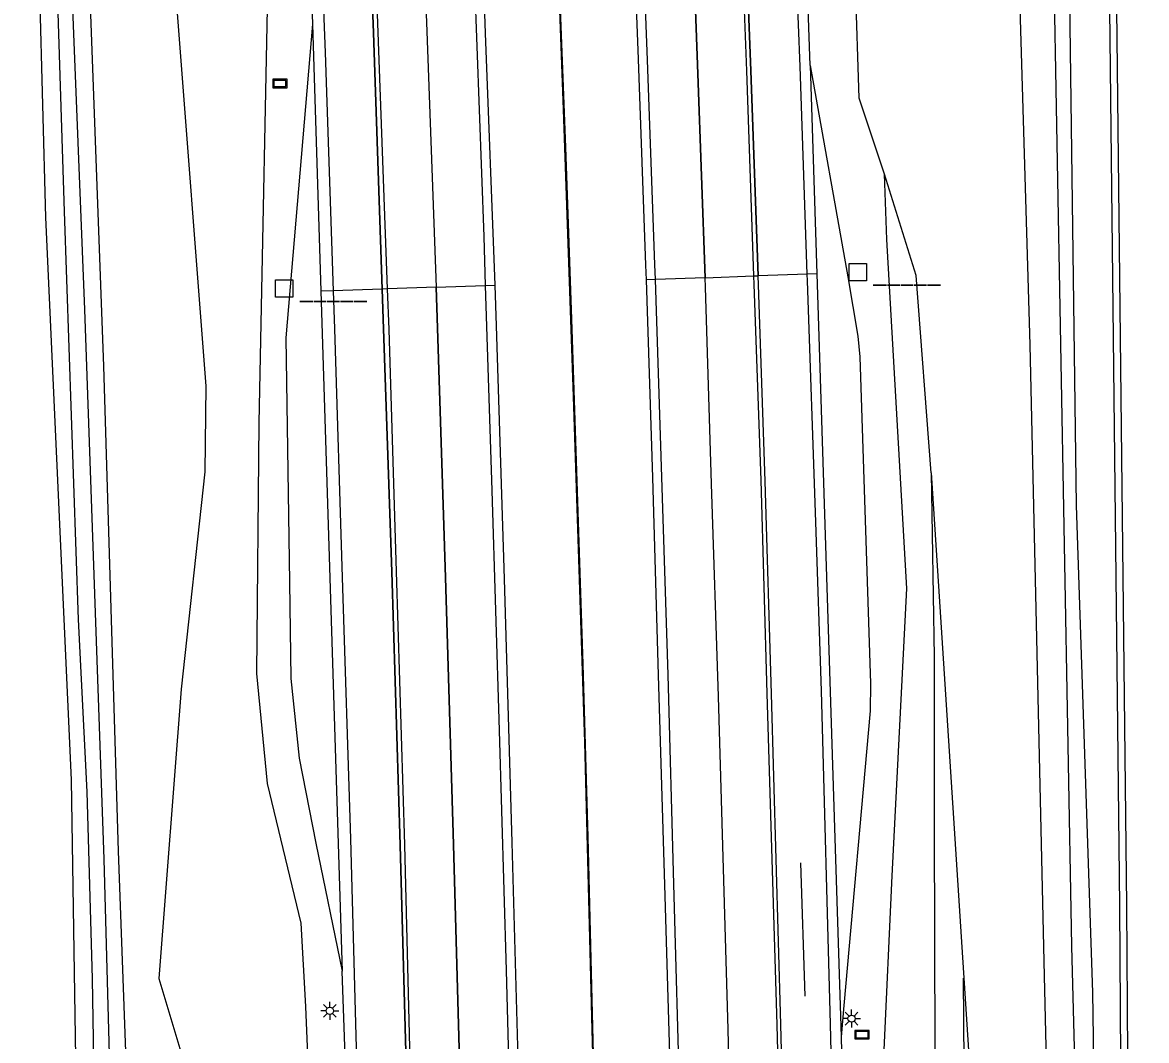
# Model space of a CAD drawing. Extents: x 133000 to 136000, y 400500 to 403500.
# Drawn here: x 133107.2 to 133185.2, y 401903.1 to 401973.7 of the extents above; entities that cross this region are included whole.
import ezdxf

# ---------------------------------------------------------------- set-up
doc = ezdxf.new("R2010")
doc.units = 0
for name, color, linetype in [('gg-afsc-lijn draadraster', 7, 'Continuous'), ('gt-knt-geleideconstructie', 7, 'Continuous'), ('gt-symb-bord', 7, 'Continuous'), ('gt-symb-hm paal', 7, 'Continuous'), ('gt-symb-lichtmast', 7, 'Continuous'), ('gx-grn-maaiveld', 7, 'Continuous'), ('gx-knt-lijn weginrichtingselement', 7, 'Continuous')]:
    doc.layers.add(name, color=color, linetype=linetype)

# ---------------------------------------------------------------- blocks, each defined once
blk = doc.blocks.new('gt0-HMpaal')
at = {"layer": 'gt-symb-hm paal'}
blk.add_lwpolyline([(-0.6, 0.6), (0.6, 0.6), (0.6, -0.6), (-0.6, -0.6)], close=True, dxfattribs=at)
blk = doc.blocks.new('gt0-BORD')
at = {"layer": 'gt-symb-bord'}
blk.add_lwpolyline([(-0.5, 0.295), (-0.5, -0.295), (0.5, -0.295), (0.5, 0.295), (-0.5, 0.295)], dxfattribs=at)
blk.add_lwpolyline([(-0.417, -0.212), (0.417, -0.212), (0.417, 0.212), (-0.417, 0.212)], close=True, dxfattribs=at)
blk = doc.blocks.new('gt0-LMAST')
at = {"layer": 'gt-symb-lichtmast'}
for p, q in [((-0.182, 0.173), (-0.447, 0.438)), ((-0.005, 0.246), (-0.005, 0.621)), ((0.172, 0.173), (0.437, 0.438)), ((-0.255, -0.004), (-0.63, -0.004)), ((-0.182, -0.181), (-0.447, -0.446)), ((-0.005, -0.254), (-0.005, -0.629)), ((0.437, -0.446), (0.172, -0.181)), ((0.245, -0.004), (0.62, -0.004))]:
    blk.add_line(p, q, dxfattribs=at)
blk.add_circle((-0.005, -0.004), 0.25, dxfattribs=at)

msp = doc.modelspace()

# ---------------------------------------------------------------- linework, layer by layer
at = {"layer": 'gg-afsc-lijn draadraster'}
msp.add_lwpolyline([(133174.016, 401805.443), (133174.136, 401808.549), (133174.159, 401809.14), (133174.172, 401813.522), (133174.109, 401818.318), (133173.692, 401850.139), (133172.627, 401894.902), (133172.575, 401901.522), (133172.528, 401907.403)], dxfattribs=at)
at = {"layer": 'gt-knt-geleideconstructie'}
msp.add_lwpolyline([(133149.363, 401793.243), (133149.083, 401805.224), (133148.887, 401817.242), (133148.636, 401829.227), (133148.416, 401841.232), (133148.091, 401853.218), (133147.822, 401865.204), (133147.496, 401877.215), (133147.225, 401889.21), (133146.87, 401901.198), (133146.493, 401917.197), (133146.145, 401929.19), (133145.738, 401941.185), (133145.363, 401953.153), (133144.94, 401965.088), (133144.484, 401977.083)], dxfattribs=at)
at = {"layer": 'gx-grn-maaiveld'}
for p, q in [((133127.358, 401973.624), (133127.939, 401955.086)), ((133161.889, 401970.754), (133162.35, 401956.298)), ((133162.35, 401956.298), (133164.04, 401903.323)), ((133127.939, 401955.086), (133129.417, 401907.897))]:
    msp.add_line(p, q, dxfattribs=at)
for points in [[(133176.05, 402057.04), (133177.396, 402032.031), (133178.512, 402008.898), (133179.703, 401989.356), (133180.341, 401940.214), (133181.464, 401906.415), (133181.539, 401901.715), (133182.254, 401857.402), (133183.35, 401809.953), (133183.229, 401809.552), (133183.03, 401809.332), (133182.798, 401809.261), (133182.54, 401809.296), (133182.302, 401809.634), (133181.77, 401846.486), (133180.249, 401901.687), (133180.03, 401909.629), (133178.78, 401979.281), (133178.419, 401989.728), (133177.792, 402004.82), (133177.249, 402019.981), (133176.408, 402036.174), (133175.693, 402050.241), (133175.359, 402057.017)], [(133146.351, 402055.862), (133146.989, 402042.445), (133147.593, 402028.479), (133148.206, 402014.746), (133148.796, 402000.86), (133149.367, 401986.341), (133149.963, 401971.194), (133150.47, 401956.9), (133150.504, 401955.876)], [(133150.439, 402056.066), (133150.913, 402045.905), (133151.57, 402031.837), (133152.248, 402016.696), (133152.92, 402000.007), (133153.564, 401984.746), (133154.094, 401970.177), (133154.598, 401956.022)], [(133154.139, 402056.25), (133154.603, 402046.055), (133155.303, 402031.823), (133155.951, 402016.736), (133156.613, 402000.091), (133157.227, 401984.859), (133157.781, 401970.375), (133158.29, 401956.154)], [(133161.889, 401970.754), (133161.382, 401985.289), (133160.739, 402000.389), (133160.074, 402016.844), (133159.413, 402032.013), (133158.774, 402046.182), (133158.241, 402056.455)], [(133128.099, 402054.964), (133128.101, 402054.915), (133128.74, 402041.054), (133129.565, 402023.279), (133130.265, 402006.486), (133130.993, 401988.979), (133131.596, 401973.015), (133132.203, 401955.236)], [(133131.81, 402055.151), (133131.816, 402055.024), (133132.441, 402041.171), (133133.263, 402023.294), (133133.974, 402006.566), (133134.689, 401989.085), (133135.302, 401973.111), (133135.93, 401955.367)], [(133135.897, 402055.357), (133135.922, 402054.854), (133136.531, 402041.262), (133137.36, 402023.486), (133138.085, 402006.765), (133138.777, 401989.132), (133139.348, 401972.996), (133140.006, 401955.51)], [(133108.363, 402054.325), (133108.468, 402052.323), (133110.209, 402015.35), (133111.655, 401982.461), (133112.857, 401949.877), (133113.884, 401916.225), (133114.467, 401900.414), (133115.394, 401875.299), (133116.395, 401826.398), (133115.699, 401816.238), (133115.91, 401815.754), (133116.719, 401815.324), (133124.581, 401816.316), (133125.023, 401816.019), (133125.204, 401815.496), (133125.11, 401810.457), (133124.98, 401810.092), (133124.48, 401809.894), (133118.918, 401810.424), (133114.126, 401811.625), (133112.802, 401812.751)], [(133112.963, 402054.452), (133114.085, 402025.85), (133117.578, 401989.274), (133117.943, 401974.682), (133119.969, 401948.497), (133119.889, 401942.54), (133118.252, 401927.473), (133116.694, 401907.374), (133118.792, 401900.446), (133119.487, 401898.152), (133122.312, 401893.701), (133123.783, 401889.955), (133123.969, 401883.825), (133125.155, 401850.739), (133126.285, 401824.409), (133126.07, 401808.221), (133125.464, 401807.237)], [(133121.296, 402054.731), (133122.517, 402034.095), (133123.546, 402004.084), (133124.348, 401981.599), (133123.643, 401945.952), (133123.481, 401928.541), (133124.211, 401920.925), (133126.555, 401911.214), (133126.865, 401905.448), (133127.29, 401895.389), (133128.724, 401847.354), (133129.414, 401810.458), (133129.765, 401808.488), (133129.93, 401807.918), (133129.99, 401802.659), (133129.505, 401793.52), (133129.915, 401767.084), (133130.438, 401731.107), (133130.443, 401730.556)], [(133123.981, 402054.757), (133124.618, 402040.726), (133125.415, 402023.421), (133126.167, 402006.041), (133126.853, 401988.792), (133127.358, 401973.624)], [(133167.047, 401963.208), (133165.283, 401968.487), (133165.029, 401976.411), (133164.634, 401985.999), (133163.742, 402003.579), (133163.113, 402018.097), (133162.041, 402032.047), (133162.118, 402036.867), (133163.133, 402041.701), (133165.122, 402042.809), (133166.748, 402041.307), (133168.46, 402036.479), (133170.348, 402028.458), (133170.988, 402020.917), (133172.554, 402019.904), (133174.556, 402019.191)], [(133179.637, 402012.29), (133179.74, 402010.493), (133182.516, 401987.151), (133183.359, 401912.431), (133183.425, 401901.755), (133183.636, 401867.984), (133185.223, 401812.521), (133184.372, 401808.818), (133182.828, 401807.782), (133181.607, 401807.848), (133180.898, 401808.562)], [(133183.938, 401902.016), (133183.859, 401912.435), (133183.016, 401987.184), (133182.183, 401997.995)], [(133110.957, 401900.388), (133110.651, 401921.172), (133108.856, 401960.206), (133108.226, 401983.696), (133107.241, 401997.394)], [(133112.209, 401900.397), (133112.096, 401907.347), (133111.728, 401920.347), (133111.132, 401932.305), (133110.159, 401960.622), (133109.124, 401993.28)], [(133110.29, 401985.155), (133111.535, 401953.808), (133112.874, 401915.654), (133113.31, 401900.406)], [(133176.44, 401974.763), (133177.12, 401951.36), (133178.099, 401908.566), (133178.26, 401901.644), (133179.216, 401860.691), (133180.337, 401813.008), (133180.436, 401810.51), (133180.898, 401808.562)], [(133127.358, 401973.624), (133127.266, 401972.538), (133125.505, 401951.847), (133125.761, 401934.892), (133125.858, 401928.206), (133126.437, 401922.678), (133127.587, 401916.769), (133129.417, 401907.897)], [(133161.889, 401970.754), (133164.498, 401956.075), (133165.189, 401951.973), (133165.345, 401950.528), (133166.068, 401927.867), (133166.043, 401925.963), (133164.214, 401905.518), (133164.04, 401903.323)], [(133169.976, 401732.377), (133169.109, 401765.25), (133168.734, 401799.659), (133169.145, 401809.488), (133168.849, 401814.908), (133168.404, 401825.818), (133167.837, 401856.684), (133166.993, 401901.918), (133167.581, 401914.498), (133168.597, 401934.441), (133167.211, 401958.665), (133167.047, 401963.208)], [(133170.288, 401942.471), (133169.239, 401956.169), (133167.047, 401963.208)], [(133154.598, 401956.022), (133151.154, 401955.899), (133150.504, 401955.876)], [(133154.598, 401956.022), (133157.959, 401956.142), (133158.29, 401956.154)], [(133157.394, 401855.941), (133157.328, 401859.155), (133156.961, 401873.55), (133156.568, 401888.599), (133156.19, 401903.839), (133155.529, 401926.953), (133155.051, 401941.724), (133154.621, 401955.376), (133154.598, 401956.022)], [(133162.35, 401956.298), (133161.677, 401956.274), (133158.29, 401956.154)], [(133161.094, 401856.022), (133161.034, 401858.812), (133160.674, 401873.791), (133160.255, 401888.751), (133159.854, 401904.18), (133159.203, 401927.149), (133158.768, 401941.899), (133158.312, 401955.528), (133158.29, 401956.154)], [(133132.203, 401955.236), (133128.805, 401955.116), (133127.939, 401955.086)], [(133135.93, 401955.367), (133132.567, 401955.248), (133132.203, 401955.236)], [(133132.203, 401955.236), (133132.297, 401952.47), (133132.868, 401935.611), (133133.451, 401916.626), (133133.918, 401898.907), (133134.496, 401876.52), (133134.825, 401863.048), (133134.972, 401856.385), (133134.993, 401855.448)], [(133135.93, 401955.367), (133139.349, 401955.487), (133140.006, 401955.51)], [(133138.725, 401855.526), (133138.706, 401856.502), (133138.52, 401863.073), (133138.223, 401876.539), (133137.628, 401899.161), (133137.149, 401916.691), (133136.579, 401935.22), (133136.03, 401952.529), (133135.93, 401955.367)], [(133140.006, 401955.51), (133140.113, 401952.671), (133140.649, 401935.129), (133141.189, 401916.824), (133141.687, 401899.334), (133142.302, 401876.699), (133142.603, 401863.517), (133142.717, 401856.878), (133142.747, 401855.61)], [(133150.504, 401955.876), (133150.955, 401942.153), (133151.353, 401928.431), (133151.789, 401913.876), (133152.253, 401898.191), (133152.613, 401883.94), (133152.952, 401869.743), (133153.291, 401855.852)], [(133170.288, 401942.471), (133172.964, 401900.965), (133173.886, 401854.111), (133174.834, 401817.956), (133176.134, 401815.052), (133177.888, 401812.555)], [(133170.288, 401942.471), (133170.487, 401929.702), (133170.48, 401917.896), (133170.539, 401902.464), (133171.233, 401863.66), (133171.471, 401829.718), (133171.878, 401823.078), (133172.733, 401818.118), (133173.1, 401812.674), (133173.124, 401809.183), (133173.169, 401807.366), (133173.729, 401805.633)], [(133130.857, 401855.362), (133130.826, 401856.732), (133130.675, 401862.836), (133130.362, 401876.635), (133129.752, 401898.785), (133129.417, 401907.897)], [(133164.04, 401903.323), (133164.366, 401888.863), (133164.766, 401873.871), (133165.114, 401859.052), (133165.186, 401856.11)]]:
    msp.add_lwpolyline(points, dxfattribs=at)
at = {"layer": 'gx-knt-lijn weginrichtingselement'}
msp.add_line((133161.548, 401906.153), (133161.232, 401915.406), dxfattribs=at)
for points in [[(133127.567, 401988.844), (133128.238, 401971.659), (133128.805, 401955.116), (133128.896, 401952.472), (133129.409, 401935.22), (133129.997, 401917.076), (133130.494, 401899.137), (133131.094, 401876.752), (133131.421, 401862.892), (133131.576, 401856.676), (133131.604, 401855.378), (133131.963, 401838.577), (133132.335, 401822.287), (133132.634, 401804.83), (133133.616, 401788.133), (133134.435, 401772.977), (133135.396, 401755.749), (133135.419, 401755.363), (133136.381, 401739.008), (133136.862, 401730.852)], [(133137.066, 401731.048), (133136.977, 401739.077), (133136.79, 401755.4), (133136.787, 401755.654), (133136.567, 401772.95), (133136.36, 401787.918), (133136.044, 401804.647), (133135.711, 401822.363), (133135.378, 401838.312), (133134.993, 401855.448), (133134.972, 401856.385), (133134.825, 401863.048), (133134.496, 401876.52), (133133.918, 401898.907), (133133.451, 401916.626), (133132.868, 401935.611), (133132.297, 401952.47), (133132.203, 401955.236), (133131.596, 401973.015), (133130.993, 401988.979)], [(133137.358, 401730.875), (133137.28, 401739.006), (133137.104, 401755.408), (133137.101, 401755.703), (133136.859, 401772.888), (133136.659, 401787.704), (133136.341, 401804.597), (133136.04, 401822.554), (133135.676, 401838.435), (133135.304, 401855.455), (133135.284, 401856.394), (133135.132, 401863.075), (133134.828, 401876.553), (133134.217, 401898.824), (133133.777, 401916.651), (133133.179, 401935.634), (133132.669, 401952.424), (133132.567, 401955.248), (133131.922, 401973.035), (133131.328, 401989.02)], [(133134.689, 401989.085), (133135.302, 401973.111), (133135.93, 401955.367), (133136.03, 401952.529), (133136.579, 401935.22), (133137.149, 401916.691), (133137.628, 401899.161), (133138.223, 401876.539), (133138.52, 401863.073), (133138.706, 401856.502), (133138.725, 401855.526), (133139.056, 401838.79), (133139.409, 401822.12), (133139.777, 401804.525), (133140.033, 401787.79), (133140.246, 401772.214), (133140.512, 401755.637), (133140.514, 401755.5), (133140.705, 401738.835), (133140.764, 401731.032)], [(133150.032, 401731.519), (133150.049, 401743.985), (133149.851, 401755.766), (133149.716, 401764.004), (133149.474, 401783.985), (133149.104, 401803.931), (133148.684, 401823.945), (133148.289, 401843.896), (133147.846, 401863.859), (133147.308, 401883.86), (133146.757, 401903.81), (133146.256, 401923.788), (133145.477, 401947.773), (133144.777, 401967.689), (133144.045, 401987.724)], [(133156.02, 401731.734), (133155.889, 401743.841), (133155.732, 401755.912), (133155.719, 401756.908), (133155.542, 401770.938), (133155.297, 401784.596), (133155.059, 401798.496), (133154.86, 401811.857), (133154.594, 401826.986), (133154.267, 401841.261), (133153.967, 401855.463), (133153.958, 401855.867), (133153.666, 401869.689), (133153.264, 401883.931), (133152.874, 401898.189), (133152.433, 401913.932), (133152.034, 401928.46), (133151.597, 401942.17), (133151.154, 401955.899), (133151.121, 401956.933), (133150.604, 401971.133), (133150.019, 401986.332)], [(133159.455, 401731.893), (133159.32, 401745.256), (133159.176, 401755.411), (133159.167, 401756.005), (133158.948, 401769.999), (133158.75, 401784.143), (133158.507, 401799.423), (133158.236, 401815.561), (133157.991, 401829.728), (133157.644, 401843.656), (133157.394, 401855.941), (133157.328, 401859.155), (133156.961, 401873.55), (133156.568, 401888.599), (133156.19, 401903.839), (133155.529, 401926.953), (133155.051, 401941.724), (133154.621, 401955.376), (133154.598, 401956.022), (133154.094, 401970.177), (133153.564, 401984.746)], [(133156.922, 401984.844), (133157.465, 401970.382), (133157.959, 401956.142), (133157.98, 401955.54), (133158.458, 401941.959), (133158.889, 401927.159), (133159.576, 401904.177), (133159.974, 401888.736), (133160.35, 401873.784), (133160.724, 401858.859), (133160.786, 401856.015), (133161.052, 401843.895), (133161.39, 401830.024), (133161.622, 401815.686), (133161.904, 401799.083), (133162.148, 401784.131), (133162.359, 401770.249), (133162.53, 401756.096), (133162.54, 401755.293), (133162.72, 401744.985), (133162.863, 401732.05)], [(133163.163, 401732.063), (133163.018, 401744.977), (133162.883, 401755.323), (133162.87, 401756.105), (133162.641, 401770.269), (133162.439, 401784.148), (133162.207, 401799.11), (133161.945, 401815.699), (133161.638, 401830.053), (133161.356, 401843.905), (133161.094, 401856.022), (133161.034, 401858.812), (133160.674, 401873.791), (133160.255, 401888.751), (133159.854, 401904.18), (133159.203, 401927.149), (133158.768, 401941.899), (133158.312, 401955.528), (133158.29, 401956.154), (133157.781, 401970.375), (133157.227, 401984.859)], [(133166.593, 401732.221), (133166.447, 401744.965), (133166.289, 401756.059), (133166.287, 401756.198), (133166.131, 401770.326), (133165.859, 401784.361), (133165.624, 401798.889), (133165.349, 401815.569), (133165.053, 401830.086), (133164.765, 401843.99), (133164.519, 401856.096), (133164.46, 401858.994), (133164.038, 401873.925), (133163.678, 401888.82), (133163.288, 401904.202), (133162.668, 401927.358), (133162.283, 401939.059), (133161.693, 401955.806), (133161.677, 401956.274), (133161.19, 401970.684), (133160.627, 401985.278)], [(133138.598, 401976.479), (133139.241, 401958.892), (133139.349, 401955.487), (133139.802, 401941.245), (133140.318, 401924.602), (133140.803, 401907.93), (133141.246, 401891.306), (133141.64, 401874.658), (133141.957, 401863.286), (133142.073, 401856.534), (133142.094, 401855.597), (133142.441, 401840.322), (133142.768, 401824.538), (133143.093, 401808.843), (133143.386, 401793.069), (133143.648, 401777.378), (133143.88, 401759.747), (133143.936, 401755.593), (133144.119, 401742.075), (133144.217, 401731.191)]]:
    msp.add_lwpolyline(points, dxfattribs=at)

# ---------------------------------------------------------------- block references
at = {"layer": 'gt-symb-bord'}
for p in [(133125.101, 401969.507), (133165.484, 401903.486)]:
    msp.add_blockref('gt0-BORD', p, dxfattribs=at)
at = {"layer": 'gt-symb-hm paal'}
for p in [(133165.201, 401956.405), (133125.404, 401955.274)]:
    msp.add_blockref('gt0-HMpaal', p, dxfattribs=at)
at = {"layer": 'gt-symb-lichtmast'}
for p in [(133128.571, 401905.141), (133164.766, 401904.598)]:
    msp.add_blockref('gt0-LMAST', p, dxfattribs=at)

# ---------------------------------------------------------------- texts
at = {"layer": 'gt-symb-hm paal'}
for p in [(133166.282, 401955.801), (133126.485, 401954.67)]:
    msp.add_text('_____', height=1.25, dxfattribs=at).set_placement(p)

doc.saveas('drawing.dxf')
